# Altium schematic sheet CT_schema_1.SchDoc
size 463 x 258 mm
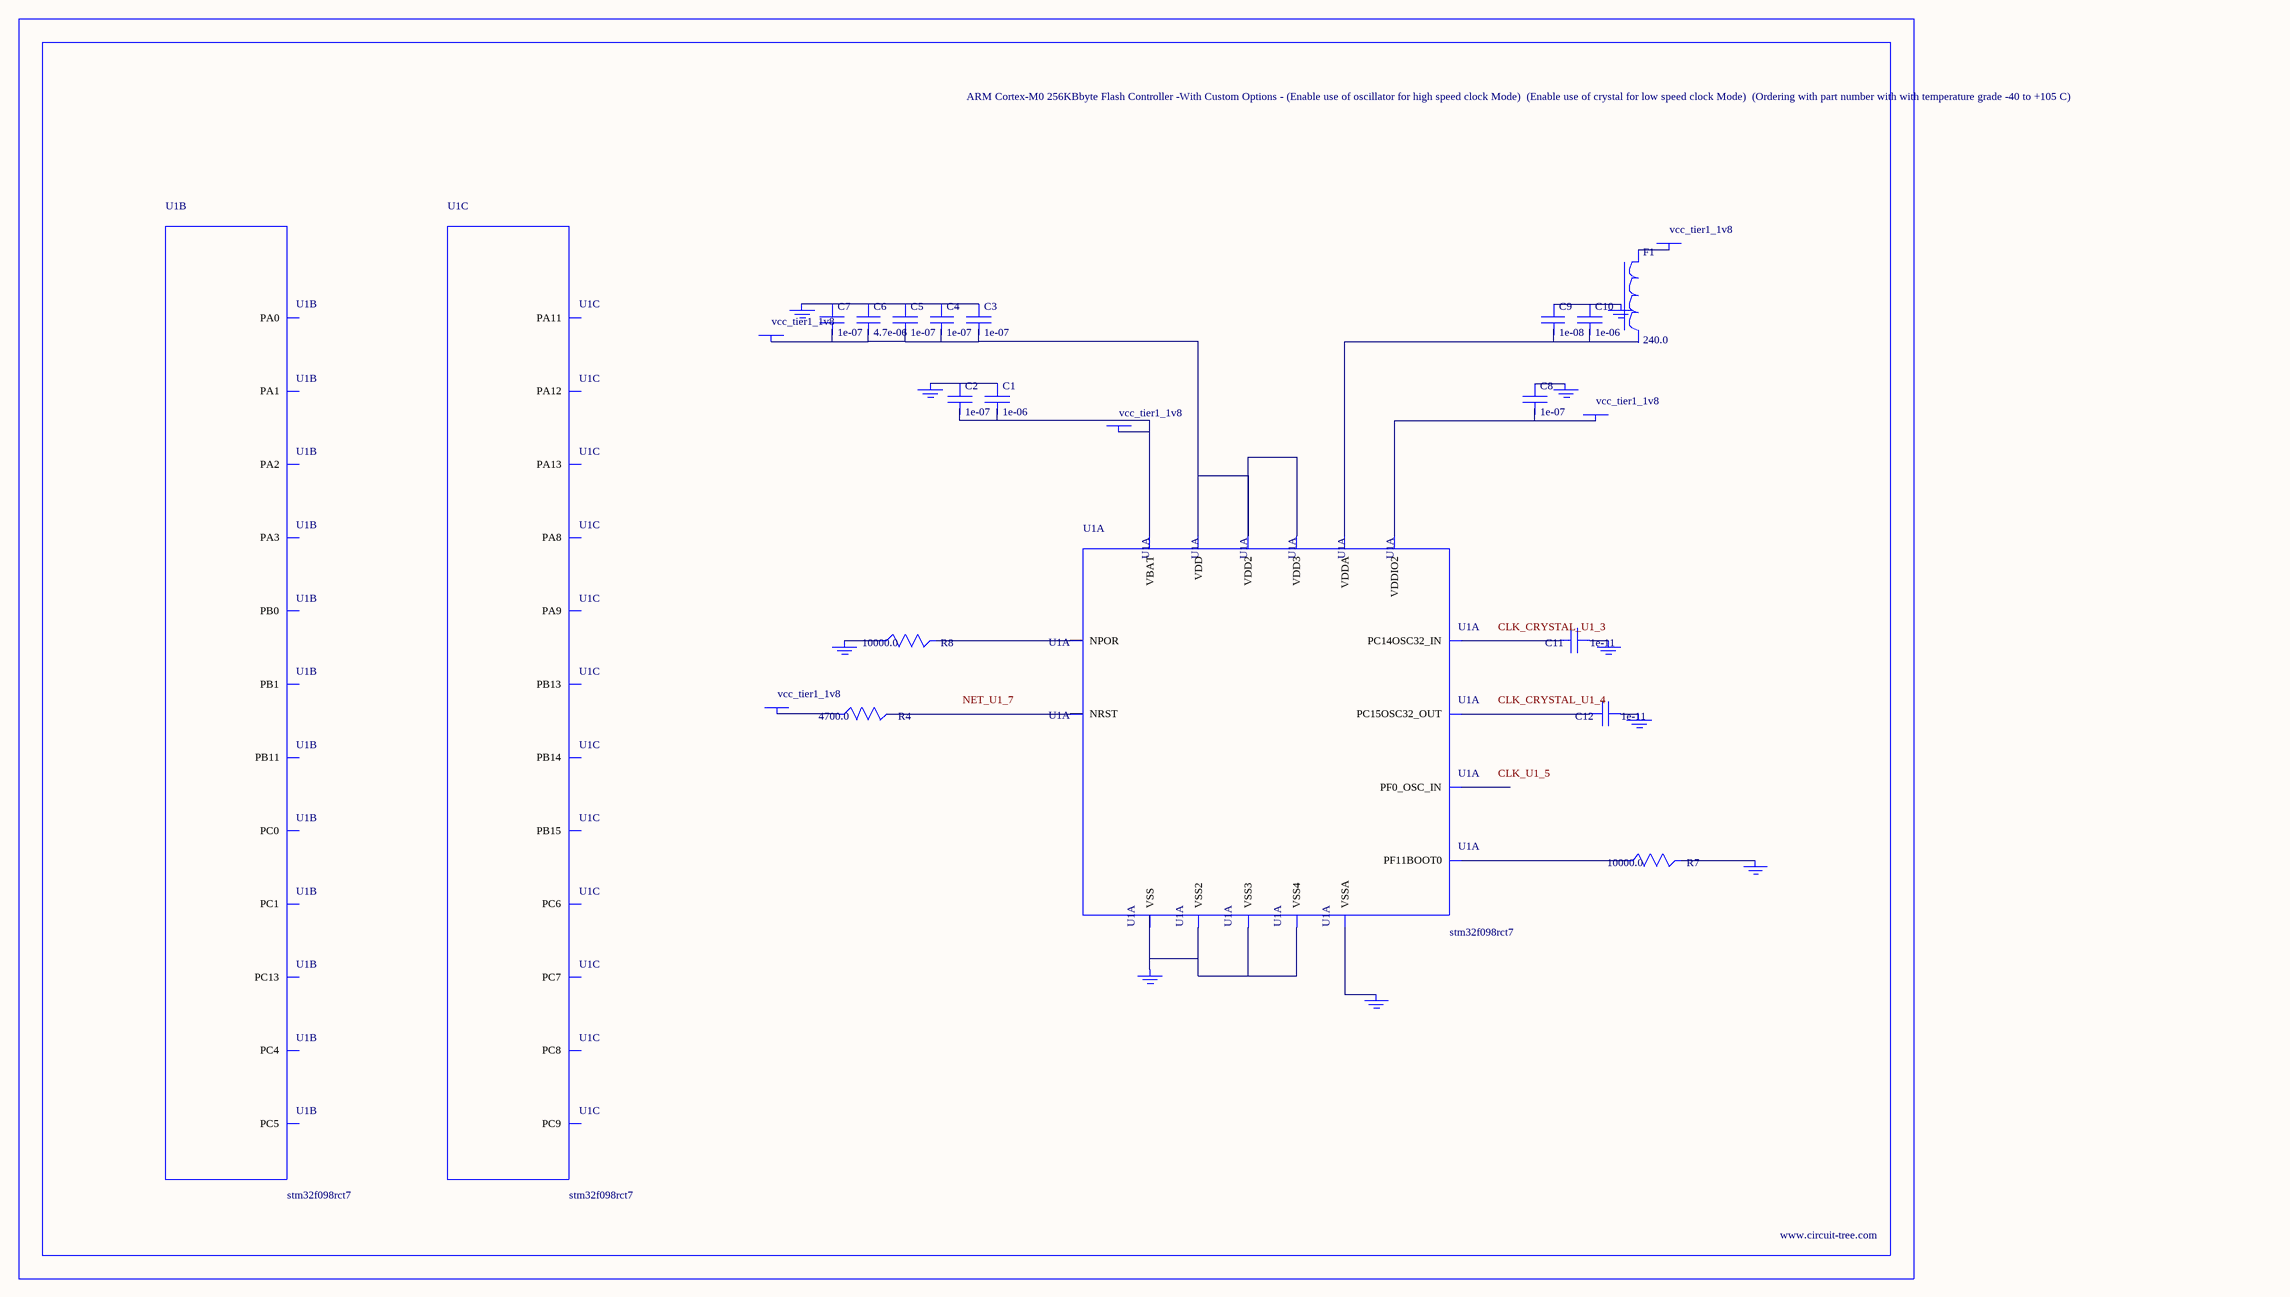
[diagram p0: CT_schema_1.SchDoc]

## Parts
BORDER0  (no value)
C1  1e-06  [C0603]
C2  1e-07  [C0603]
C3  1e-07  [C0603]
C4  1e-07  [C0603]
C5  1e-07  [C0603]
C6  4.7e-06  [C0603]
C7  1e-07  [C0603]
C8  1e-07  [C0603]
C9  1e-08  [C0603]
C10  1e-06  [C0603]
C11  1e-11  [C0402]
C12  1e-11  [C0402]
F1  240.0  [L0603]
GND_INSTANCE_0_0  (no value)
GND_INSTANCE_0_1  (no value)
GND_INSTANCE_0_2  (no value)
GND_INSTANCE_0_3  (no value)
GND_INSTANCE_0_4  (no value)
GND_INSTANCE_0_5  (no value)
GND_INSTANCE_0_6  (no value)
GND_INSTANCE_0_7  (no value)
GND_INSTANCE_0_8  (no value)
GND_INSTANCE_0_9  (no value)
POWER_INSTANCE_0_0  vcc_tier1_1v8
POWER_INSTANCE_0_1  vcc_tier1_1v8
POWER_INSTANCE_0_2  vcc_tier1_1v8
POWER_INSTANCE_0_3  vcc_tier1_1v8
POWER_INSTANCE_0_4  vcc_tier1_1v8
R4  4700.0  [R0603]
R7  10000.0  [R0603]
R8  10000.0  [R0603]
U1  stm32f098rct7  [LQFP64]  (parts A,B,C of 7)

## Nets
NetC1_1: C1.1 C2.1 GND_INSTANCE_0_0.0(GND)
NetC1_2: C1.2 C2.2 POWER_INSTANCE_0_0.0(PWR) U1.1(VBAT)
NetC3_1: C3.1 C4.1 C5.1 C6.1 C7.1 GND_INSTANCE_0_5.0(GND)
NetC3_2: C3.2 C4.2 C5.2 C6.2 C7.2 POWER_INSTANCE_0_2.0(PWR) U1.19(VDD) U1.32(VDD2) U1.64(VDD3)
NetC8_1: C8.1 GND_INSTANCE_0_7.0(GND)
NetC8_2: C8.2 POWER_INSTANCE_0_3.0(PWR) U1.48(VDDIO2)
NetC9_1: C9.1 C10.1 GND_INSTANCE_0_4.0(GND)
NetC9_2: C9.2 C10.2 U1.13(VDDA)
NetC11_1: C11.1 GND_INSTANCE_0_1.0(GND)
NetC11_2: C11.2 U1.3(PC14OSC32_IN)
NetC12_1: C12.1 GND_INSTANCE_0_2.0(GND)
NetC12_2: C12.2 U1.4(PC15OSC32_OUT)
NetF1_1: F1.1 POWER_INSTANCE_0_1.0(PWR)
NetGND_INSTANCE_0_3_0: GND_INSTANCE_0_3.0(GND) U1.12(VSSA)
NetGND_INSTANCE_0_6_0: GND_INSTANCE_0_6.0(GND) R8.1
NetGND_INSTANCE_0_8_0: GND_INSTANCE_0_8.0(GND) R7.2
NetGND_INSTANCE_0_9_0: GND_INSTANCE_0_9.0(GND) U1.18(VSS) U1.31(VSS2) U1.47(VSS3) U1.63(VSS4)
NetPOWER_INSTANCE_0_4_0: POWER_INSTANCE_0_4.0(PWR) R4.1
NetR4_2: R4.2 U1.7(NRST)
NetR7_1: R7.1 U1.60(PF11BOOT0)
NetR8_2: R8.2 U1.28(NPOR)

Not connected (* = marked no-connect by the designer): F1 2; U1 2(PC13) 5(PF0_OSC_IN) 8(PC0) 9(PC1) 14(PA0) 15(PA1) 16(PA2) 17(PA3) 24(PC4) 25(PC5) 26(PB0) 27(PB1) 30(PB11) 34(PB13) 35(PB14) 36(PB15) 37(PC6) 38(PC7) 39(PC8) 40(PC9) 41(PA8) 42(PA9) 44(PA11) 45(PA12) 46(PA13)

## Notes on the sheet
- Labels drawn without touching a wire or pin: CLK_CRYSTAL_U1_3, CLK_CRYSTAL_U1_4, CLK_U1_5, NET_U1_7

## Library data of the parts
BORDER0 = BORDER_PAGE0
C1 C10 = C0603C105K3RACTU
C2-C5 C7 C8 = 06035C104K4Z2A
C6 = GRM188R6YA475KE15D
C9 = 06035C103K4Z2A
C11 C12 = C0402C100K3GACTU
F1 = Z0603C241ASMST
GND_INSTANCE_0_0-GND_INSTANCE_0_9 = GND
POWER_INSTANCE_0_0-POWER_INSTANCE_0_4 = PWR
R4 = RC0603JR-074K7L
R7 R8 = RC0603JR-0710KL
